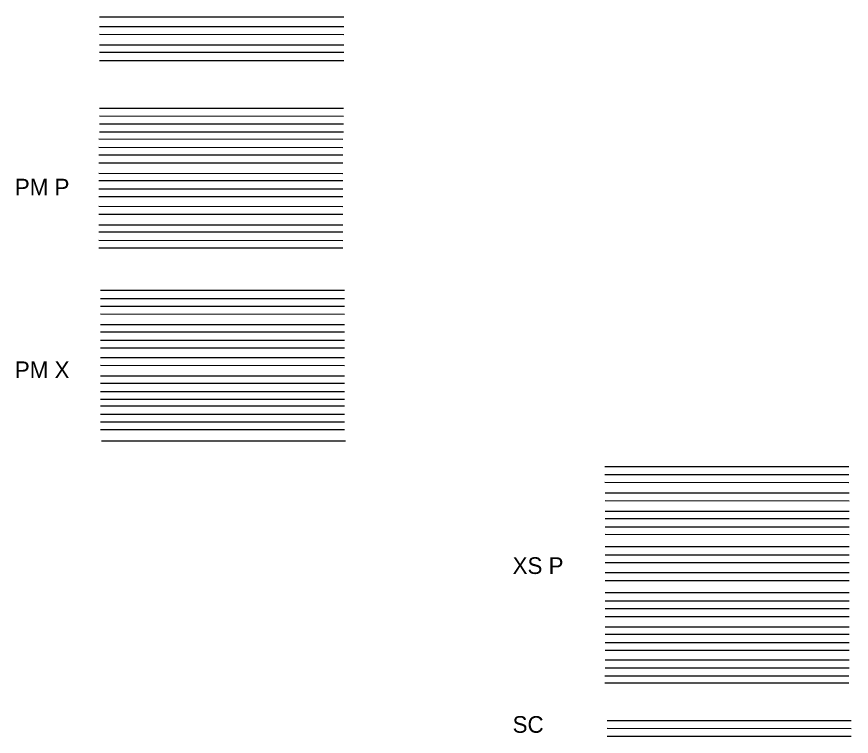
# Model space of a CAD drawing. Extents: x 19437 to 1370217, y 6871 to 405972.
# Drawn here: x 19437 to 22436, y 6871 to 9457 of the extents above; entities that cross this region are included whole.
import ezdxf

# ---------------------------------------------------------------- set-up
doc = ezdxf.new("R2010")
doc.units = 0
for name, color, linetype in [('Default', 7, 'Continuous'), ('MT_P_Signal', 7, 'Continuous'), ('MT_P_Stop_Line', 7, 'Continuous'), ('MT_P_Temp_Road', 7, 'Continuous'), ('MT_P_Text', 7, 'Continuous'), ('MT_P_Traffic_Attenuator', 7, 'Continuous'), ('MT_P_Work_Area', 7, 'Continuous'), ('PM_P_Cells', 7, 'Continuous'), ('PM_P_Channelizing_Line', 7, 'Continuous'), ('PM_P_Chevron_Line', 7, 'Continuous'), ('PM_P_CL_Dashed', 7, 'Continuous'), ('PM_P_CL_Double_Solid', 7, 'Continuous'), ('PM_P_CL_Pass_Proh_Lt', 7, 'Continuous'), ('PM_P_CL_Pass_Proh_Rt', 7, 'Continuous'), ('PM_P_Crosswalk', 7, 'Continuous'), ('PM_P_Dotted_Line', 7, 'Continuous'), ('PM_P_Edge_Line', 7, 'Continuous'), ('PM_P_Island', 7, 'Continuous'), ('PM_P_Lane_Line', 7, 'Continuous'), ('PM_P_Parking_Lot_Stall', 7, 'Continuous'), ('PM_P_Removal', 7, 'Continuous'), ('PM_P_Stop_Line', 7, 'Continuous'), ('PM_P_Text', 7, 'Continuous'), ('PM_P_Transverse_Line', 7, 'Continuous'), ('PM_P_Yield_Line', 7, 'Continuous'), ('PM_X_Cells', 7, 'Continuous'), ('PM_X_Channelizing_Line', 7, 'Continuous'), ('PM_X_Chevron_Line', 7, 'Continuous'), ('PM_X_CL_Dashed', 7, 'Continuous'), ('PM_X_CL_Double_Solid', 7, 'Continuous'), ('PM_X_CL_Pass_Proh_Lt', 7, 'Continuous'), ('PM_X_CL_Pass_Proh_Rt', 7, 'Continuous'), ('PM_X_Crosswalk', 7, 'Continuous'), ('PM_X_Dotted_Line', 7, 'Continuous'), ('PM_X_Edge_Line', 7, 'Continuous'), ('PM_X_Island', 7, 'Continuous'), ('PM_X_Lane_Line', 7, 'Continuous'), ('PM_X_Misc', 7, 'Continuous'), ('PM_X_Parking_Lot_Stall', 7, 'Continuous'), ('PM_X_Stop_Line', 7, 'Continuous'), ('PM_X_Surveyed_Line', 7, 'Continuous'), ('PM_X_Transverse_Line', 7, 'Continuous'), ('PM_X_Yield_Line', 7, 'Continuous'), ('SC_Shading1', 7, 'Continuous'), ('SC_Shading2', 7, 'Continuous'), ('SC_Shading3', 7, 'Continuous'), ('XS_P_Annotation', 7, 'Continuous'), ('XS_P_Barrier', 7, 'Continuous'), ('XS_P_Barrier_Surface', 7, 'Continuous'), ('XS_P_Boundary', 7, 'Continuous'), ('XS_P_Curb', 7, 'Continuous'), ('XS_P_Curb_Surface', 7, 'Continuous'), ('XS_P_Ditch_Bottom', 7, 'Continuous'), ('XS_P_Earthwork_Shapes', 7, 'Continuous'), ('XS_P_Excavation_Limits', 7, 'Continuous'), ('XS_P_Finished_Grade', 7, 'Continuous'), ('XS_P_Finished_Grade_Seeded', 7, 'Continuous'), ('XS_P_Headwall', 7, 'Continuous'), ('XS_P_Headwall_Surface', 7, 'Continuous'), ('XS_P_Pavt_Layers', 7, 'Continuous'), ('XS_P_Pavt_Surface', 7, 'Continuous'), ('XS_P_Ret_Wall', 7, 'Continuous'), ('XS_P_Ret_Wall_Surface', 7, 'Continuous'), ('XS_P_Shoulder_Layers', 7, 'Continuous'), ('XS_P_Shoulder_Surface', 7, 'Continuous'), ('XS_P_Special_Benching', 7, 'Continuous'), ('XS_P_Subgrade', 7, 'Continuous'), ('XS_P_Text_Info', 7, 'Continuous'), ('XS_P_Text_MarkedPoint', 7, 'Continuous'), ('XS_P_Text_WarningMsg', 7, 'Continuous'), ('XS_P_Undercut', 7, 'Continuous'), ('XS_P_Undercut2', 7, 'Continuous')]:
    doc.layers.add(name, color=color, linetype=linetype)

msp = doc.modelspace()

# ---------------------------------------------------------------- linework, layer by layer
at = {"layer": 'MT_P_Signal'}
msp.add_lwpolyline([(19734.8, 9457.1), (19734.8, 9457.1), (20612.1, 9456.9), (20612.1, 9456.9)], dxfattribs=at)
at = {"layer": 'MT_P_Stop_Line'}
msp.add_lwpolyline([(19734.8, 9422), (19734.8, 9422), (20612.1, 9421.8), (20612.1, 9421.8)], dxfattribs=at)
at = {"layer": 'MT_P_Temp_Road'}
msp.add_lwpolyline([(19734.8, 9393.8), (19734.8, 9393.8), (20612.1, 9393.6), (20612.1, 9393.6)], dxfattribs=at)
at = {"layer": 'MT_P_Text'}
msp.add_lwpolyline([(19734.8, 9356), (19734.8, 9356), (20612.1, 9355.8), (20612.1, 9355.8)], dxfattribs=at)
at = {"layer": 'MT_P_Traffic_Attenuator'}
msp.add_lwpolyline([(19734.8, 9329.9), (19734.8, 9329.9), (20612.1, 9329.7), (20612.1, 9329.7)], dxfattribs=at)
at = {"layer": 'MT_P_Work_Area'}
msp.add_lwpolyline([(19734.8, 9299.9), (19734.8, 9299.9), (20612.1, 9299.7), (20612.1, 9299.7)], dxfattribs=at)
at = {"layer": 'PM_P_Cells'}
msp.add_lwpolyline([(19731.9, 9017.7), (19731.9, 9017.7), (20609.1, 9017.4), (20609.1, 9017.4)], dxfattribs=at)
at = {"layer": 'PM_P_Channelizing_Line'}
msp.add_lwpolyline([(19734.2, 9128.9), (19734.2, 9128.9), (20611.5, 9128.6), (20611.5, 9128.6)], dxfattribs=at)
at = {"layer": 'PM_P_Chevron_Line'}
msp.add_lwpolyline([(19731.9, 8987.7), (19731.9, 8987.7), (20609.1, 8987.5), (20609.1, 8987.5)], dxfattribs=at)
at = {"layer": 'PM_P_CL_Dashed'}
msp.add_lwpolyline([(19731.9, 8960.3), (19731.9, 8960.3), (20609.1, 8960.1), (20609.1, 8960.1)], dxfattribs=at)
at = {"layer": 'PM_P_CL_Double_Solid'}
msp.add_lwpolyline([(19734.2, 9100.3), (19734.2, 9100.3), (20611.5, 9100.1), (20611.5, 9100.1)], dxfattribs=at)
at = {"layer": 'PM_P_CL_Pass_Proh_Lt'}
msp.add_lwpolyline([(19731.9, 8932.1), (19731.9, 8932.1), (20609.1, 8931.8), (20609.1, 8931.8)], dxfattribs=at)
at = {"layer": 'PM_P_CL_Pass_Proh_Rt'}
msp.add_lwpolyline([(19731.9, 8894.3), (19731.9, 8894.3), (20609.1, 8894), (20609.1, 8894)], dxfattribs=at)
at = {"layer": 'PM_P_Crosswalk'}
msp.add_lwpolyline([(19734.2, 9071.8), (19734.2, 9071.8), (20611.5, 9071.6), (20611.5, 9071.6)], dxfattribs=at)
at = {"layer": 'PM_P_Dotted_Line'}
msp.add_lwpolyline([(19731.9, 8868.2), (19731.9, 8868.2), (20609.1, 8868), (20609.1, 8868)], dxfattribs=at)
at = {"layer": 'PM_P_Edge_Line'}
msp.add_lwpolyline([(19731.9, 8838.2), (19731.9, 8838.2), (20609.1, 8838), (20609.1, 8838)], dxfattribs=at)
at = {"layer": 'PM_P_Island'}
msp.add_lwpolyline([(19731.9, 8810.9), (19731.9, 8810.9), (20609.1, 8810.6), (20609.1, 8810.6)], dxfattribs=at)
at = {"layer": 'PM_P_Lane_Line'}
msp.add_lwpolyline([(19731.9, 8775.7), (19731.9, 8775.7), (20609.1, 8775.5), (20609.1, 8775.5)], dxfattribs=at)
at = {"layer": 'PM_P_Parking_Lot_Stall'}
msp.add_lwpolyline([(19731.9, 8747.5), (19731.9, 8747.5), (20609.1, 8747.3), (20609.1, 8747.3)], dxfattribs=at)
at = {"layer": 'PM_P_Removal'}
msp.add_lwpolyline([(19731.9, 8709.7), (19731.9, 8709.7), (20609.1, 8709.5), (20609.1, 8709.5)], dxfattribs=at)
at = {"layer": 'PM_P_Stop_Line'}
msp.add_lwpolyline([(19734.2, 9043.3), (19734.2, 9043.3), (20611.5, 9043.1), (20611.5, 9043.1)], dxfattribs=at)
at = {"layer": 'PM_P_Text'}
msp.add_lwpolyline([(19731.9, 8683.6), (19731.9, 8683.6), (20609.1, 8683.4), (20609.1, 8683.4)], dxfattribs=at)
at = {"layer": 'PM_P_Transverse_Line'}
msp.add_lwpolyline([(19731.9, 8653.6), (19731.9, 8653.6), (20609.1, 8653.4), (20609.1, 8653.4)], dxfattribs=at)
at = {"layer": 'PM_P_Yield_Line'}
msp.add_lwpolyline([(19731.9, 8626.3), (19731.9, 8626.3), (20609.1, 8626.1), (20609.1, 8626.1)], dxfattribs=at)
at = {"layer": 'PM_X_Cells'}
for points in [[(19737.7, 8474.4), (19737.7, 8474.4), (20615, 8474.2), (20615, 8474.2)], [(19741.6, 7933.4), (19741.6, 7933.4), (20618.9, 7933.2), (20618.9, 7933.2)]]:
    msp.add_lwpolyline(points, dxfattribs=at)
at = {"layer": 'PM_X_Channelizing_Line'}
msp.add_lwpolyline([(19737.7, 8444.4), (19737.7, 8444.4), (20615, 8444.2), (20615, 8444.2)], dxfattribs=at)
at = {"layer": 'PM_X_Chevron_Line'}
msp.add_lwpolyline([(19737.7, 8417.1), (19737.7, 8417.1), (20615, 8416.9), (20615, 8416.9)], dxfattribs=at)
at = {"layer": 'PM_X_CL_Dashed'}
msp.add_lwpolyline([(19737.7, 8388.8), (19737.7, 8388.8), (20615, 8388.6), (20615, 8388.6)], dxfattribs=at)
at = {"layer": 'PM_X_CL_Double_Solid'}
msp.add_lwpolyline([(19737.7, 8351), (19737.7, 8351), (20615, 8350.8), (20615, 8350.8)], dxfattribs=at)
at = {"layer": 'PM_X_CL_Pass_Proh_Lt'}
msp.add_lwpolyline([(19737.7, 8325), (19737.7, 8325), (20615, 8324.7), (20615, 8324.7)], dxfattribs=at)
at = {"layer": 'PM_X_CL_Pass_Proh_Rt'}
msp.add_lwpolyline([(19737.7, 8295), (19737.7, 8295), (20615, 8294.8), (20615, 8294.8)], dxfattribs=at)
at = {"layer": 'PM_X_Crosswalk'}
msp.add_lwpolyline([(19737.7, 8267.6), (19737.7, 8267.6), (20615, 8267.4), (20615, 8267.4)], dxfattribs=at)
at = {"layer": 'PM_X_Dotted_Line'}
msp.add_lwpolyline([(19737.7, 8232.5), (19737.7, 8232.5), (20615, 8232.3), (20615, 8232.3)], dxfattribs=at)
at = {"layer": 'PM_X_Edge_Line'}
msp.add_lwpolyline([(19737.7, 8204.2), (19737.7, 8204.2), (20615, 8204), (20615, 8204)], dxfattribs=at)
at = {"layer": 'PM_X_Island'}
msp.add_lwpolyline([(19737.7, 8166.4), (19737.7, 8166.4), (20615, 8166.2), (20615, 8166.2)], dxfattribs=at)
at = {"layer": 'PM_X_Lane_Line'}
msp.add_lwpolyline([(19737.7, 8140.4), (19737.7, 8140.4), (20615, 8140.2), (20615, 8140.2)], dxfattribs=at)
at = {"layer": 'PM_X_Misc'}
msp.add_lwpolyline([(19737.7, 8110.4), (19737.7, 8110.4), (20615, 8110.2), (20615, 8110.2)], dxfattribs=at)
at = {"layer": 'PM_X_Parking_Lot_Stall'}
msp.add_lwpolyline([(19737.7, 8083), (19737.7, 8083), (20615, 8082.8), (20615, 8082.8)], dxfattribs=at)
at = {"layer": 'PM_X_Stop_Line'}
msp.add_lwpolyline([(19737.7, 8058.9), (19737.7, 8058.9), (20615, 8058.7), (20615, 8058.7)], dxfattribs=at)
at = {"layer": 'PM_X_Surveyed_Line'}
msp.add_lwpolyline([(19737.7, 8029), (19737.7, 8029), (20615, 8028.8), (20615, 8028.8)], dxfattribs=at)
at = {"layer": 'PM_X_Transverse_Line'}
msp.add_lwpolyline([(19737.7, 8001.6), (19737.7, 8001.6), (20615, 8001.4), (20615, 8001.4)], dxfattribs=at)
at = {"layer": 'PM_X_Yield_Line'}
msp.add_lwpolyline([(19737.7, 7973.3), (19737.7, 7973.3), (20615, 7973.1), (20615, 7973.1)], dxfattribs=at)
at = {"layer": 'SC_Shading1'}
msp.add_lwpolyline([(21558.3, 6928.2), (21558.3, 6928.2), (22435.6, 6928), (22435.6, 6928)], dxfattribs=at)
at = {"layer": 'SC_Shading2'}
msp.add_lwpolyline([(21558.3, 6899.7), (21558.3, 6899.7), (22435.6, 6899.5), (22435.6, 6899.5)], dxfattribs=at)
at = {"layer": 'SC_Shading3'}
msp.add_lwpolyline([(21558.3, 6871.2), (21558.3, 6871.2), (22435.6, 6871), (22435.6, 6871)], dxfattribs=at)
at = {"layer": 'XS_P_Annotation'}
msp.add_lwpolyline([(21549.8, 7840.9), (21549.8, 7840.9), (22427.1, 7840.7), (22427.1, 7840.7)], dxfattribs=at)
at = {"layer": 'XS_P_Barrier'}
msp.add_lwpolyline([(21551, 7746.3), (21551, 7746.3), (22428.2, 7746.1), (22428.2, 7746.1)], dxfattribs=at)
at = {"layer": 'XS_P_Barrier_Surface'}
msp.add_lwpolyline([(21551, 7718.1), (21551, 7718.1), (22428.2, 7717.8), (22428.2, 7717.8)], dxfattribs=at)
at = {"layer": 'XS_P_Boundary'}
msp.add_lwpolyline([(21551, 7680.3), (21551, 7680.3), (22428.2, 7680), (22428.2, 7680)], dxfattribs=at)
at = {"layer": 'XS_P_Curb'}
msp.add_lwpolyline([(21551, 7654.2), (21551, 7654.2), (22428.2, 7654), (22428.2, 7654)], dxfattribs=at)
at = {"layer": 'XS_P_Curb_Surface'}
msp.add_lwpolyline([(21551, 7624.2), (21551, 7624.2), (22428.2, 7624), (22428.2, 7624)], dxfattribs=at)
at = {"layer": 'XS_P_Ditch_Bottom'}
msp.add_lwpolyline([(21551, 7596.9), (21551, 7596.9), (22428.2, 7596.6), (22428.2, 7596.6)], dxfattribs=at)
at = {"layer": 'XS_P_Earthwork_Shapes'}
msp.add_lwpolyline([(21551, 7553.2), (21551, 7553.2), (22428.2, 7553), (22428.2, 7553)], dxfattribs=at)
at = {"layer": 'XS_P_Excavation_Limits'}
msp.add_lwpolyline([(21551, 7523.2), (21551, 7523.2), (22428.2, 7523), (22428.2, 7523)], dxfattribs=at)
at = {"layer": 'XS_P_Finished_Grade'}
msp.add_lwpolyline([(21549.8, 7812.3), (21549.8, 7812.3), (22427.1, 7812.1), (22427.1, 7812.1)], dxfattribs=at)
at = {"layer": 'XS_P_Finished_Grade_Seeded'}
msp.add_lwpolyline([(21551, 7495.9), (21551, 7495.9), (22428.2, 7495.7), (22428.2, 7495.7)], dxfattribs=at)
at = {"layer": 'XS_P_Headwall'}
msp.add_lwpolyline([(21551, 7459.7), (21551, 7459.7), (22428.2, 7459.5), (22428.2, 7459.5)], dxfattribs=at)
at = {"layer": 'XS_P_Headwall_Surface'}
msp.add_lwpolyline([(21551, 7431.1), (21551, 7431.1), (22428.2, 7430.9), (22428.2, 7430.9)], dxfattribs=at)
at = {"layer": 'XS_P_Pavt_Layers'}
msp.add_lwpolyline([(21551, 7387.5), (21551, 7387.5), (22428.2, 7387.3), (22428.2, 7387.3)], dxfattribs=at)
at = {"layer": 'XS_P_Pavt_Surface'}
msp.add_lwpolyline([(21549.8, 7783.8), (21549.8, 7783.8), (22427.1, 7783.6), (22427.1, 7783.6)], dxfattribs=at)
at = {"layer": 'XS_P_Ret_Wall'}
msp.add_lwpolyline([(21551, 7357.5), (21551, 7357.5), (22428.2, 7357.3), (22428.2, 7357.3)], dxfattribs=at)
at = {"layer": 'XS_P_Ret_Wall_Surface'}
msp.add_lwpolyline([(21551, 7330.1), (21551, 7330.1), (22428.2, 7329.9), (22428.2, 7329.9)], dxfattribs=at)
at = {"layer": 'XS_P_Shoulder_Layers'}
msp.add_lwpolyline([(21551, 7301.9), (21551, 7301.9), (22428.2, 7301.7), (22428.2, 7301.7)], dxfattribs=at)
at = {"layer": 'XS_P_Shoulder_Surface'}
msp.add_lwpolyline([(21551, 7264.1), (21551, 7264.1), (22428.2, 7263.9), (22428.2, 7263.9)], dxfattribs=at)
at = {"layer": 'XS_P_Special_Benching'}
msp.add_lwpolyline([(21551, 7238), (21551, 7238), (22428.2, 7237.8), (22428.2, 7237.8)], dxfattribs=at)
at = {"layer": 'XS_P_Subgrade'}
msp.add_lwpolyline([(21551, 7208), (21551, 7208), (22428.2, 7207.8), (22428.2, 7207.8)], dxfattribs=at)
at = {"layer": 'XS_P_Text_Info'}
msp.add_lwpolyline([(21551, 7180.7), (21551, 7180.7), (22428.2, 7180.5), (22428.2, 7180.5)], dxfattribs=at)
at = {"layer": 'XS_P_Text_MarkedPoint'}
msp.add_lwpolyline([(21551, 7145.5), (21551, 7145.5), (22428.2, 7145.3), (22428.2, 7145.3)], dxfattribs=at)
at = {"layer": 'XS_P_Text_WarningMsg'}
msp.add_lwpolyline([(21551, 7117.3), (21551, 7117.3), (22428.2, 7117.1), (22428.2, 7117.1)], dxfattribs=at)
at = {"layer": 'XS_P_Undercut'}
msp.add_lwpolyline([(21549.8, 7088.9), (21549.8, 7088.9), (22427.1, 7088.7), (22427.1, 7088.7)], dxfattribs=at)
at = {"layer": 'XS_P_Undercut2'}
msp.add_lwpolyline([(21549.8, 7062.8), (21549.8, 7062.8), (22427.1, 7062.6), (22427.1, 7062.6)], dxfattribs=at)

# ---------------------------------------------------------------- texts
at = {"layer": 'Default'}
for s, p in [('PM P', (19430.6, 8814.6)), ('PM X', (19430.6, 8158.2)), ('XS P', (21218.8, 7454.4)), ('SC', (21218.8, 6883.6))]:
    msp.add_text(s, height=60, dxfattribs=at).set_placement(p)

doc.saveas('drawing.dxf')
